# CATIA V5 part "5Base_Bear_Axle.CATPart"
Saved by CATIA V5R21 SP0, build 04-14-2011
Part number: Base_Bear_Axle
Bounding box of the stored display mesh (mm): x -15.05 to 15.05, y -15.05 to 15.05, z 0 to 11
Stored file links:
  K:\Arm_Detailed_Design_Assembly_Manu\5Base_Bear_Axle.CATPart
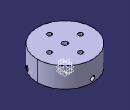
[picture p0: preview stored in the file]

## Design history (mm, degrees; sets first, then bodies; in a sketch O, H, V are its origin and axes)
Body1 (main body)
  Sketch1 on xy-plane, origin (0, 0, 0), H (1, 0, 0), V (0, 1, 0)
    circle A1 centre (0, 0) radius 15.05
    radius A1 = 15.05
  Pad1: profile Sketch1, direction (0, 0, 1), length 11
  Sketch2 on start face of Pad1, origin (0, 0, 0), H (1, 0, 0), V (0, -1, 0)
    circle A1 centre (0, 0) radius 11.05
    reference projected circle E1 centre (0, 0) radius 15.05 from edge [start face of Pad1 | face of Pad1 from Sketch1.A1]
    distance A1 E1 = 4
  Pocket1: profile Sketch2, direction (0, 0, 1), up to end face of Pad1, offset -3
  Sketch3 on end face of Pad1, origin (0, 0, 11), H (1, 0, 0), V (0, 1, 0)
    circle A1 centre (0, 8.5) radius 1.25
    point P1 (0, 8.5)
    circle A2 centre (8.5, 0) radius 1.25
    point P2 (8.5, 0)
    circle A3 centre (0, -8.5) radius 1.25
    point P3 (0, -8.5)
    circle A4 centre (-8.5, 0) radius 1.25
    point P4 (-8.5, 0)
    point P5 (-7.25, 0)
    circle A5 centre (0, 0) radius 1.5
    radius A1 = 1.25
    radius A2 = 1.25
    radius A3 = 1.25
    radius A4 = 1.25
    distance P1 H = 8.5
    distance P2 V = 8.5
    distance P3 H = 8.5
    distance V P4 = 8.5
    radius A5 = 1.5
    coincidence: P1 V, P2 H, P3 V, P4 H, A4 P5, P5 H
  Pocket2: profile Sketch3, direction (0, 0, -1), through (limit type 3)
  DatumCurve1
  Sketch4 on start face of Pad1, origin (0, 0, 0), H (1, 0, 0), V (0, -1, 0)
    point P1 (14.25, 0)
    circle A1 centre (0, 13) radius 1.25
    point P2 (0, 13)
    circle A2 centre (-11.2583, -6.5) radius 1.25
    circle A3 centre (11.2583, -6.5) radius 1.25
    radius A1 = 1.25
    distance P2 H = 13
    coincidence: P1 H, P2 V
  Pocket3: profile Sketch4, direction (0, 0, 1), length 4
  Plane1: type Angle, RefPlane zx-plane, Direction Z axis, Angle 60
  Sketch5 on Plane1, origin (0, 0, 0), H (-0.5, -0.866, 0), V (0, 0, 1)
    circle A1 centre (0, 2) radius 1.25
    point P1 (0, 2)
    reference projected line E1 (-15.05, 0) -> (15.05, 0) from edge [start face of Pad1 | face of Pad1 from Sketch1.A1]
    distance P1 E1 = 2
    radius A1 = 1.25
    coincidence: P1 V
  Pocket4: profile Sketch5, direction (0.866, -0.5, 0), length 40
  Plane2: type Offset, RefPlane start face of Pad1, Offset 2, reversed
  Plane3: type Angle, RefPlane Plane1, Direction Z axis, Angle -120
  Sketch6 on Plane3, origin (0, 0, 0), H (-0.5, 0.866, 0), V (0, 0, 1)
    circle A1 centre (0, 2) radius 1.25
    point P1 (0, 2)
    reference projected line E1 (-15.05, 0) -> (15.05, 0) from edge [start face of Pad1 | face of Pad1 from Sketch1.A1]
    radius A1 = 1.25
    distance P1 E1 = 2
    coincidence: P1 V
  Pocket5: profile Sketch6, direction (-0.866, -0.5, 0), length 40
  Plane4: type Angle, RefPlane zx-plane, Direction Z axis, Angle 0
  Sketch7 on Plane4, origin (0, 0, 0), H (-1, 0, 0), V (0, 0, 1)
    circle A1 centre (0, 2) radius 1.25
    point P1 (0, 2)
    reference projected line E1 (-15.05, 0) -> (15.05, 0) from edge [start face of Pad1 | face of Pad1 from Sketch1.A1]
    radius A1 = 1.25
    distance P1 E1 = 2
    coincidence: P1 V
  Pocket6: profile Sketch7, direction (0, 1, 0), length 40
Body2
  Sketch8 on Plane2, origin (0, 0, -2), H (1, 0, 0), V (0, -1, 0)
    circle A1 centre (0, 0) radius 10
    circle A2 centre (0, 0) radius 17
    point P1 (-11.75, 0)
    circle A3 centre (0, 13) radius 1.25
    point P2 (0, 13)
    reference projected circle E1 centre (0, 13) radius 1.25 from edge [start face of Pad1 | face of Pocket3 from Sketch4.A1]
    circle A4 centre (11.2583, -6.5) radius 1.25
    circle A5 centre (-11.2583, -6.5) radius 1.25
    reference projected circle E2 centre (11.2583, -6.5) radius 1.25 from edge [start face of Pad1 | face of Pocket3 from Sketch4.A3]
    reference projected circle E3 centre (-11.2583, -6.5) radius 1.25 from edge [start face of Pad1 | face of Pocket3 from Sketch4.A2]
    radius A1 = 10
    radius A2 = 17
    coincidence: P2 V, A3 E1, A4 E2, A5 E3
  Pad2: profile Sketch8, direction (0, 0, -1), length 3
